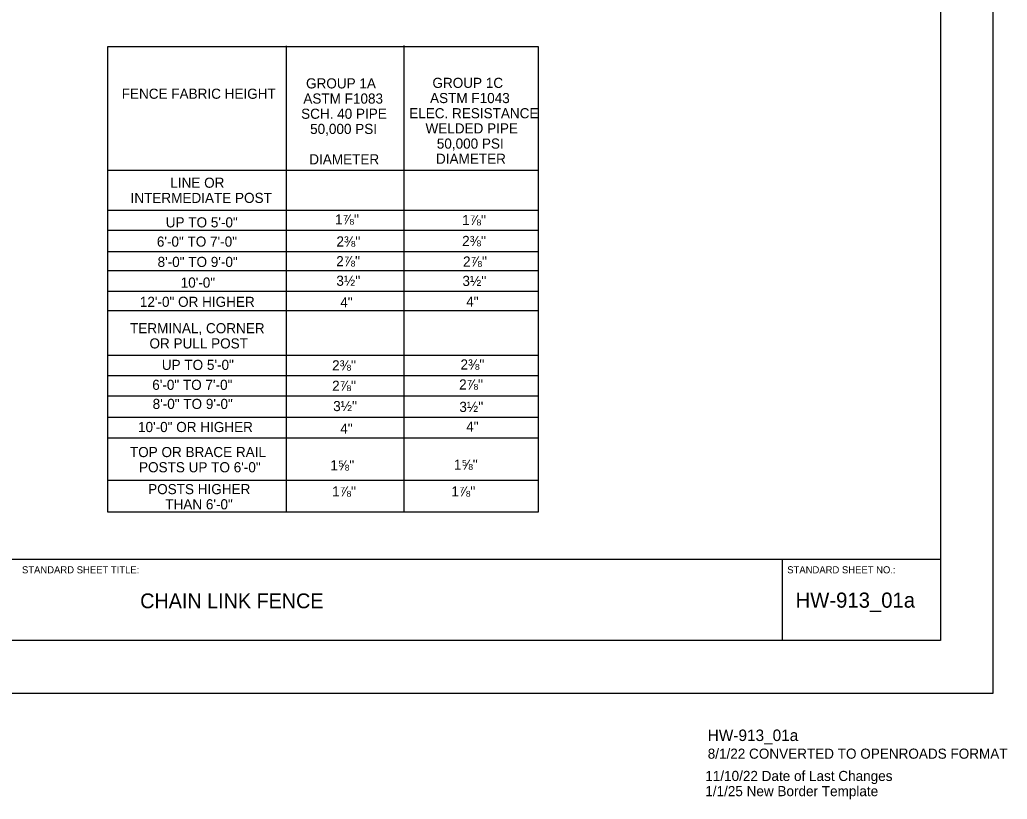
# Model space of a CAD drawing. Extents: x 0 to 2.85, y -0.1 to 1.83.
# Drawn here: x 1.871 to 2.847, y -0.105 to 0.666 of the extents above; entities that cross this region are included whole.
import ezdxf

# ---------------------------------------------------------------- set-up
doc = ezdxf.new("R2010")
doc.units = 0
for name, color, linetype in [('BDR_Inner_Perimeter', 7, 'Continuous'), ('BDR_Outer_Perimeter', 7, 'Continuous'), ('BDR_Title_Block', 7, 'Continuous'), ('Chart', 7, 'Continuous'), ('CT_CSHT_GeneralLabel', 7, 'Continuous'), ('CT_Dimensions', 7, 'Continuous'), ('Default', 7, 'Continuous'), ('sb_Existing Structural Steel', 7, 'Continuous')]:
    doc.layers.add(name, color=color, linetype=linetype)

msp = doc.modelspace()

# ---------------------------------------------------------------- linework, layer by layer
at = {"layer": 'BDR_Inner_Perimeter'}
msp.add_lwpolyline([(0.13539, 1.78125), (2.78123, 1.78125), (2.78123, 0.05208), (0.13539, 0.05208)], close=True, dxfattribs=at)
at = {"layer": 'BDR_Outer_Perimeter'}
msp.add_lwpolyline([(0, 0), (2.83333, 0), (2.83333, 1.83333), (0, 1.83333)], close=True, dxfattribs=at)
at = {"layer": 'BDR_Title_Block'}
for p, q in [((2.78123, 0.13208), (0.13539, 0.13208)), ((2.62461, 0.13208), (2.62461, 0.05208))]:
    msp.add_line(p, q, dxfattribs=at)
at = {"layer": 'Chart'}
for p, q in [((2.1343, 0.63974), (2.1343, 0.17904)), ((2.25059, 0.63997), (2.25059, 0.17923)), ((2.38349, 0.63901), (2.38349, 0.17931)), ((1.95812, 0.51703), (2.38367, 0.51703)), ((1.95811, 0.47731), (2.38366, 0.47731)), ((1.95772, 0.4575), (2.38275, 0.4575)), ((1.95803, 0.43644), (2.38385, 0.43644)), ((1.95781, 0.41793), (2.38385, 0.41793)), ((1.95781, 0.3975), (2.38317, 0.3975)), ((1.95781, 0.37821), (2.38334, 0.37821)), ((1.95831, 0.33429), (2.38359, 0.33429)), ((1.95831, 0.31409), (2.3832, 0.31409)), ((1.95844, 0.29406), (2.38353, 0.29406)), ((1.95803, 0.27284), (2.38353, 0.27284)), ((1.95817, 0.25242), (2.38352, 0.25242)), ((1.95824, 0.21077), (2.38331, 0.21077))]:
    msp.add_line(p, q, dxfattribs=at)
msp.add_lwpolyline([(1.95818, 0.63901), (2.38349, 0.63901), (2.38349, 0.17885), (1.95818, 0.17885)], close=True, dxfattribs=at)
at = {"layer": 'sb_Existing Structural Steel'}
msp.add_line((1.95817, 0.25242), (2.38329, 0.25242), dxfattribs=at)

# ---------------------------------------------------------------- texts
at = {"layer": 'BDR_Title_Block'}
for s, height, p in [('STANDARD SHEET TITLE:', 0.007, (1.87316, 0.11858)), ('STANDARD SHEET NO.:', 0.007, (2.62978, 0.11858)), ('HW-913_01a', 0.015, (2.638, 0.08458))]:
    msp.add_text(s, height=height, dxfattribs=at).set_placement(p)
at = {"layer": 'CT_CSHT_GeneralLabel'}
for s, p in [('LINE OR ', (2.01983, 0.49952)), ('INTERMEDIATE POST', (1.98053, 0.48452)), ('UP TO 5\'-0"', (2.0153, 0.46036)), ('6\'-0" TO 7\'-0"', (2.0065, 0.44135)), ('8\'-0" TO 9\'-0"', (2.00722, 0.42128)), ('10\'-0"', (2.03006, 0.40086)), ('12\'-0" OR HIGHER', (1.9897, 0.38185)), ('TERMINAL, CORNER', (1.98003, 0.35576)), ('OR PULL POST', (1.99922, 0.34076)), ('UP TO 5\'-0"', (2.01143, 0.31955)), ('6\'-0" TO 7\'-0"', (2.00195, 0.29983)), ('8\'-0" TO 9\'-0"', (2.00233, 0.28097)), ('10\'-0" OR HIGHER', (1.98788, 0.25815)), ('TOP OR BRACE RAIL', (1.97989, 0.2334)), ('POSTS UP TO 6\'-0"', (1.98889, 0.2184)), ('POSTS HIGHER ', (1.9979, 0.19679)), ('  THAN 6\'-0"', (2.00741, 0.18179))]:
    msp.add_text(s, height=0.01, dxfattribs=at).set_placement(p)
at = {"layer": 'CT_Dimensions'}
for s, p in [('GROUP 1A', (2.15401, 0.59768)), ('GROUP 1C', (2.279, 0.59819)), ('FENCE FABRIC HEIGHT', (1.97178, 0.58745)), ('ASTM F1083', (2.15135, 0.58268)), ('ASTM F1043', (2.27663, 0.58319)), ('SCH. 40 PIPE', (2.14913, 0.56768)), ('ELEC. RESISTANCE ', (2.25601, 0.56819)), ('50,000 PSI', (2.15803, 0.55268)), ('WELDED PIPE', (2.27214, 0.55319)), ('50,000 PSI', (2.2833, 0.53819)), ('DIAMETER', (2.15723, 0.52268)), ('DIAMETER', (2.28251, 0.52319)), ("1⅞'' ", (2.1827, 0.46325)), ("1⅞'' ", (2.30833, 0.46262)), ("2⅜'' ", (2.18408, 0.44149)), ("2⅜'' ", (2.30835, 0.44199)), ("2⅞'' ", (2.18385, 0.42198)), ("2⅞'' ", (2.30925, 0.42162)), ("3½'' ", (2.18399, 0.40265)), ("3½'' ", (2.30865, 0.40251)), ('4"', (2.18787, 0.38135)), ('4"', (2.31239, 0.38193)), ("2⅜'' ", (2.17981, 0.31908)), ("2⅜'' ", (2.30673, 0.31991)), ("2⅞'' ", (2.17981, 0.29889)), ("2⅞'' ", (2.30539, 0.30019)), ("3½'' ", (2.18086, 0.27884)), ("3½'' ", (2.30558, 0.27805)), ('4"', (2.18787, 0.25661)), ('4"', (2.31239, 0.25853)), ("1⅝'' ", (2.17803, 0.22038)), ("1⅝'' ", (2.3002, 0.22103)), ("1⅞'' ", (2.17981, 0.19453)), ("1⅞'' ", (2.29773, 0.19453))]:
    msp.add_text(s, height=0.01, dxfattribs=at).set_placement(p)
at = {"layer": 'Default'}
for s, height, p in [('CHAIN LINK FENCE', 0.0146088, (1.99002, 0.08408)), ('HW-913_01a', 0.011362, (2.55118, -0.04714)), ('8/1/22 CONVERTED TO OPENROADS FORMAT ', 0.01, (2.55115, -0.06462)), ('11/10/22 Date of Last Changes', 0.01, (2.54874, -0.08663)), ('1/1/25 New Border Template', 0.01, (2.54874, -0.10163))]:
    msp.add_text(s, height=height, dxfattribs=at).set_placement(p)

doc.saveas('drawing.dxf')
